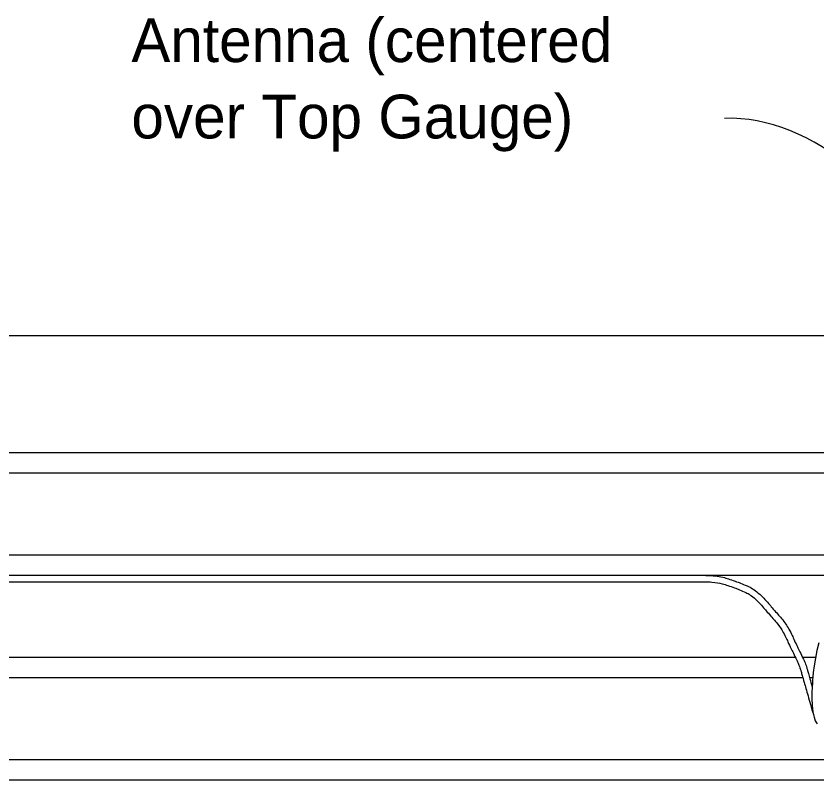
# Model space of a CAD drawing. Extents: x 0 to 36.1, y -3.7 to 15.
# Drawn here: x 13.382 to 15.23, y 11.346 to 13.107 of the extents above; entities that cross this region are included whole.
import ezdxf

# ---------------------------------------------------------------- set-up
doc = ezdxf.new("R2010")
doc.units = 0
for name, color, linetype in [('Dimension', 7, 'Continuous'), ('Leader', 7, 'Continuous'), ('Miscellaneous', 7, 'Continuous'), ('PileConc', 7, 'Continuous'), ('PrestressSteel', 7, 'Continuous')]:
    doc.layers.add(name, color=color, linetype=linetype)

msp = doc.modelspace()

# ---------------------------------------------------------------- linework, layer by layer
at = {"layer": 'Leader'}
msp.add_ellipse((15.0739, 10.8491), major_axis=(0.0578, -2.0219), ratio=0.416452, start_param=2.427672, end_param=3.141387, dxfattribs=at)
at = {"layer": 'Miscellaneous'}
for p, q in [((10.9471, 11.8176), (14.9491, 11.8176)), ((10.9471, 11.8026), (14.9491, 11.8026))]:
    msp.add_line(p, q, dxfattribs=at)
msp.add_lwpolyline([(15.2337, 11.6623), (15.2294, 11.6445), (15.2259, 11.6266), (15.2231, 11.609), (15.2212, 11.5936), (15.2202, 11.5838), (15.2195, 11.5755), (15.219, 11.5686), (15.2185, 11.5597), (15.2181, 11.5478), (15.218, 11.5335), (15.2186, 11.5176), (15.2201, 11.5028), (15.2228, 11.4902), (15.2257, 11.4821), (15.2297, 11.4754)], dxfattribs=at)
for points in [[(14.9491, 11.8176), (14.9586, 11.8176), (14.9684, 11.8178), (14.988, 11.8169), (14.9981, 11.8162), (15.0179, 11.812), (15.0274, 11.8088), (15.0459, 11.8024), (15.0552, 11.7991), (15.0736, 11.791), (15.0826, 11.7861), (15.0991, 11.7732), (15.106, 11.7658), (15.1191, 11.7513), (15.1253, 11.7439), (15.1378, 11.7296), (15.1444, 11.7225), (15.1568, 11.7069), (15.1624, 11.6982), (15.1717, 11.6806), (15.1757, 11.6717), (15.1837, 11.6544), (15.1879, 11.6459), (15.1965, 11.6285), (15.2007, 11.6196), (15.2059, 11.6054), (15.2073, 11.6005), (15.2099, 11.5913), (15.2132, 11.5796), (15.2166, 11.5679), (15.2186, 11.5608)], [(14.9491, 11.8026), (14.9685, 11.8026), (14.9873, 11.8032), (15.0137, 11.7975), (15.0226, 11.7946), (15.0407, 11.7883), (15.0498, 11.7851), (15.0667, 11.7776), (15.0746, 11.7733), (15.0886, 11.7623), (15.0952, 11.7554), (15.1077, 11.7415), (15.1138, 11.7342), (15.1267, 11.7195), (15.1331, 11.7126), (15.1446, 11.6982), (15.1495, 11.6906), (15.1582, 11.6742), (15.162, 11.6656), (15.1701, 11.648), (15.1745, 11.6392), (15.183, 11.622), (15.1869, 11.6136), (15.1916, 11.6007), (15.1929, 11.5964), (15.1955, 11.5872), (15.1994, 11.5733), (15.2086, 11.541), (15.2165, 11.5133), (15.2218, 11.4948)]]:
    msp.add_open_spline(points, degree=3, dxfattribs=at)
at = {"layer": 'PileConc'}
msp.add_line((19.6923, 12.3693), (10.9471, 12.3693), dxfattribs=at)
at = {"layer": 'PrestressSteel'}
for p, q in [((10.9471, 12.1005), (19.7548, 12.1005)), ((10.9471, 12.0536), (15.3647, 12.0536)), ((10.9471, 11.8645), (15.4196, 11.8645)), ((10.9471, 11.8176), (15.4146, 11.8176)), ((10.9471, 11.6286), (15.1797, 11.6286)), ((15.1963, 11.6286), (15.2262, 11.6286)), ((10.9471, 11.5817), (15.197, 11.5817)), ((15.2126, 11.5817), (15.22, 11.5817)), ((10.9471, 11.3927), (15.3173, 11.3927)), ((10.9471, 11.3458), (15.3065, 11.3458))]:
    msp.add_line(p, q, dxfattribs=at)

# ---------------------------------------------------------------- texts
at = {"layer": 'Dimension'}
for s, p in [('Antenna (centered', (13.6485, 13.0007)), ('over Top Gauge)', (13.6485, 12.8247))]:
    msp.add_text(s, height=0.1008, dxfattribs=at).set_placement(p)

doc.saveas('drawing.dxf')
